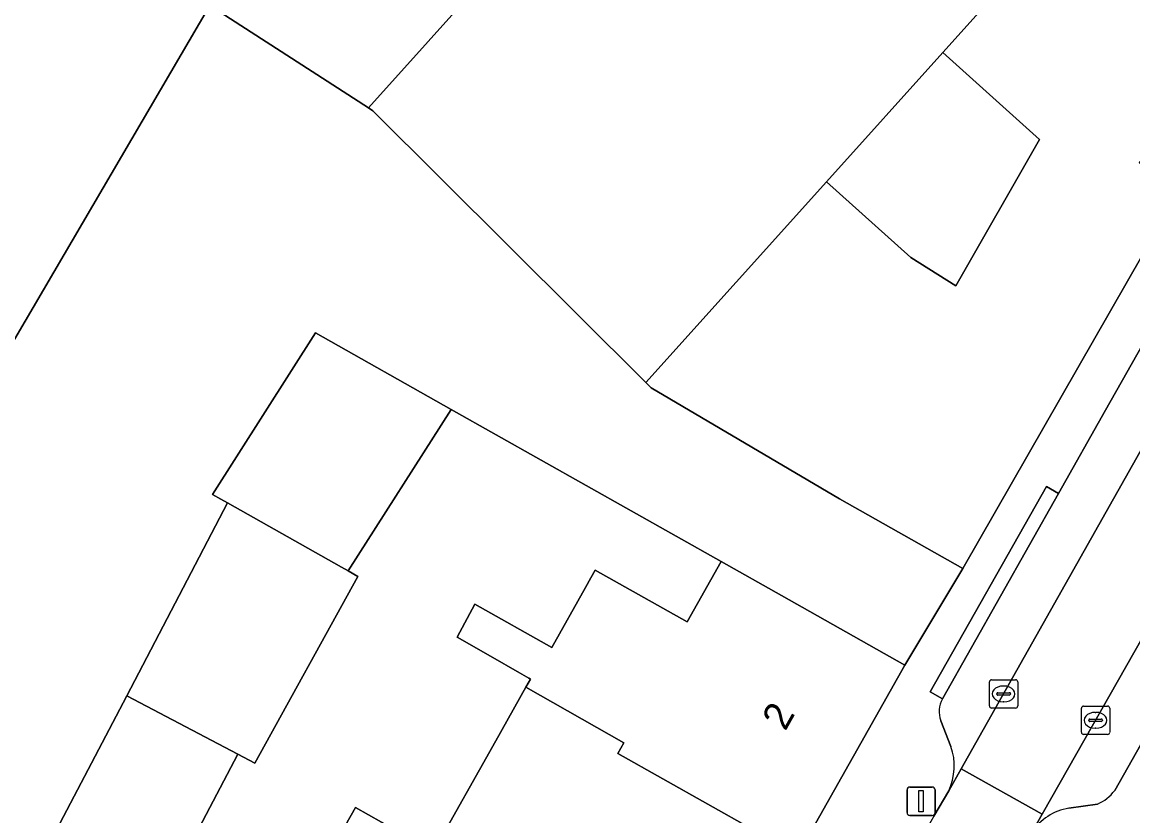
# Model space of a CAD drawing. Extents: x 161798 to 162385, y 382315 to 382833.
# Drawn here: x 161998.86 to 162038.1, y 382696.04 to 382724.06 of the extents above; entities that cross this region are included whole.
import ezdxf

# ---------------------------------------------------------------- set-up
doc = ezdxf.new("R2010")
doc.units = 0
for name, color, linetype in [('IMGEO_Erf', 7, 'Continuous'), ('IMGEO_Kolk', 7, 'Continuous'), ('IMGEO_Lichtmast', 7, 'Continuous'), ('IMGEO_Pand', 7, 'Continuous'), ('IMGEO_Pand_nummerreeks', 7, 'Continuous'), ('IMGEO_Parkeervlak_open', 7, 'Continuous'), ('IMGEO_Rijbaan_lokaal_open', 7, 'Continuous'), ('IMGEO_Voetpad_open', 7, 'Continuous')]:
    doc.layers.add(name, color=color, linetype=linetype)

msp = doc.modelspace()

# ---------------------------------------------------------------- linework, layer by layer
at = {"layer": 'IMGEO_Erf'}
for points in [[(161996.854, 382709.902), (162005.49, 382724.651), (162000, 382728.195), (161996.847, 382730.23), (162000, 382733.772), (162004.032, 382738.302), (161999.682, 382742.186), (161998.309, 382743.412), (162000, 382745.307), (162001.581, 382747.078), (162000, 382748.49), (161998.309, 382750)], [(162009.735, 382694.733), (162010.637, 382696.335), (162013.398, 382694.78), (162015.595, 382698.684), (162016.663, 382700.581), (162016.823, 382700.865), (162016.766, 382700.898), (162016.434, 382701.087), (162015.405, 382701.673), (162014.233, 382702.34), (162014.854, 382703.511), (162017.571, 382701.981), (162018.762, 382704.095), (162018.959, 382704.445), (162019.109, 382704.711), (162022.353, 382702.884), (162023.554, 382705.016), (162014.021, 382710.386), (162010.382, 382704.681), (162010.717, 382704.492), (162007.082, 382697.894), (162006.484, 382698.209), (162003.37, 382692.292)]]:
    msp.add_lwpolyline(points, dxfattribs=at)
msp.add_lwpolyline([(162031.391, 382722.985), (162027.277, 382718.416), (162030.255, 382715.747), (162031.855, 382714.755), (162034.809, 382719.922)], close=True, dxfattribs=at)
at = {"layer": 'IMGEO_Kolk'}
for p, q in [((162033.037, 382699.914), (162033.037, 382700.766)), ((162033.112, 382700.84), (162033.964, 382700.84)), ((162033.525, 382700.62), (162033.55, 382700.62)), ((162034.038, 382700.766), (162034.038, 382699.914)), ((162033.296, 382700.334), (162033.296, 382700.346)), ((162033.734, 382700.297), (162033.336, 382700.297)), ((162033.339, 382700.383), (162033.737, 382700.383)), ((162033.78, 382700.346), (162033.78, 382700.334)), ((162033.964, 382699.84), (162033.112, 382699.84)), ((162033.548, 382700.06), (162033.523, 382700.06)), ((162036.286, 382698.984), (162036.286, 382699.836)), ((162036.361, 382699.91), (162037.213, 382699.91)), ((162037.287, 382699.836), (162037.287, 382698.984)), ((162036.588, 382699.453), (162036.986, 382699.453)), ((162036.774, 382699.69), (162036.799, 382699.69)), ((162036.545, 382699.404), (162036.545, 382699.416)), ((162036.983, 382699.367), (162036.585, 382699.367)), ((162036.797, 382699.13), (162036.772, 382699.13)), ((162037.029, 382699.416), (162037.029, 382699.404)), ((162037.213, 382698.91), (162036.361, 382698.91))]:
    msp.add_line(p, q, dxfattribs=at)
for points in [[(162033.037, 382699.914), (162033.037, 382700.766)], [(162033.112, 382700.84), (162033.964, 382700.84)], [(162034.038, 382700.766), (162034.038, 382699.914)], [(162033.964, 382699.84), (162033.112, 382699.84)], [(162036.286, 382698.984), (162036.286, 382699.836)], [(162036.361, 382699.91), (162037.213, 382699.91)], [(162037.287, 382699.836), (162037.287, 382698.984)], [(162037.213, 382698.91), (162036.361, 382698.91)]]:
    msp.add_lwpolyline(points, dxfattribs=at)
for centre, radius, start, end in [((162033.114, 382700.764), 0.0765, 91.552, 178.448), ((162033.114, 382700.764), 0.0765, 91.552, 178.448), ((162033.962, 382700.764), 0.0765, 1.552, 88.448), ((162033.962, 382700.764), 0.0765, 1.552, 88.448), ((162033.336, 382700.343), 0.0403, 85.8775, 175.7526), ((162033.333, 382700.333), 0.0366, 178.938, 274.7102), ((162033.737, 382700.34), 0.043, 264.8664, 352.4533), ((162033.741, 382700.345), 0.0386, 1.7309, 96.639), ((162033.114, 382699.916), 0.0765, 181.552, 268.448), ((162033.114, 382699.916), 0.0765, 181.552, 268.448), ((162033.962, 382699.916), 0.0765, 271.552, 358.448), ((162033.962, 382699.916), 0.0765, 271.552, 358.448), ((162036.363, 382699.834), 0.0765, 91.552, 178.448), ((162036.363, 382699.834), 0.0765, 91.552, 178.448), ((162037.211, 382699.834), 0.0765, 1.552, 88.448), ((162037.211, 382699.834), 0.0765, 1.552, 88.448), ((162036.585, 382699.413), 0.0403, 85.8775, 175.7526), ((162036.99, 382699.415), 0.0386, 1.7309, 96.639), ((162036.582, 382699.403), 0.0366, 178.938, 274.7102), ((162036.986, 382699.41), 0.043, 264.8664, 352.4533), ((162036.363, 382698.986), 0.0765, 181.552, 268.448), ((162036.363, 382698.986), 0.0765, 181.552, 268.448), ((162037.211, 382698.986), 0.0765, 271.552, 358.448), ((162037.211, 382698.986), 0.0765, 271.552, 358.448)]:
    msp.add_arc(centre, radius, start, end, dxfattribs=at)
for centre, major_axis, ratio, start_param, end_param in [((162033.524, 382700.34), (-0.387, 0.002), 0.722429, 4.712389, 7.853982), ((162033.549, 382700.34), (-0.39, 0.002), 0.717154, 1.570796, 4.712389), ((162036.773, 382699.41), (-0.387, 0.002), 0.722429, 4.712389, 7.853982), ((162036.798, 382699.41), (-0.39, 0.002), 0.717154, 1.570796, 4.712389)]:
    msp.add_ellipse(centre, major_axis=major_axis, ratio=ratio, start_param=start_param, end_param=end_param, dxfattribs=at)
at = {"layer": 'IMGEO_Lichtmast'}
for p, q in [((162030.127, 382696.15), (162030.127, 382696.95)), ((162030.127, 382696.95), (162030.127, 382696.15)), ((162030.227, 382697.05), (162031.017, 382697.05)), ((162031.017, 382697.05), (162030.227, 382697.05)), ((162031.117, 382696.95), (162031.117, 382696.15)), ((162031.117, 382696.15), (162031.117, 382696.95)), ((162031.017, 382696.05), (162030.227, 382696.05)), ((162030.227, 382696.05), (162031.017, 382696.05))]:
    msp.add_line(p, q, dxfattribs=at)
msp.add_lwpolyline([(162030.547, 382696.925), (162030.697, 382696.925), (162030.697, 382696.175), (162030.547, 382696.175), (162030.547, 382696.925)], dxfattribs=at)
for centre, start, end in [((162030.227, 382696.95), 90, 180), ((162030.227, 382696.95), 90, 180), ((162031.017, 382696.95), 0, 90), ((162031.017, 382696.95), 360, 90), ((162030.227, 382696.15), 180, 270), ((162030.227, 382696.15), 180, 270), ((162031.017, 382696.15), 270, 0), ((162031.017, 382696.15), 270, 0)]:
    msp.add_arc(centre, 0.1, start, end, dxfattribs=at)
at = {"layer": 'IMGEO_Pand'}
for points in [[(162027.754, 382739.543), (162022.858, 382743.945), (162005.49, 382724.651), (162011.093, 382721.034)], [(162038.012, 382730.344), (162027.754, 382739.543), (162011.093, 382721.034), (162011.249, 382720.933), (162020.899, 382711.331), (162027.277, 382718.416), (162031.391, 382722.985)], [(162043.809, 382725.145), (162038.012, 382730.344), (162031.391, 382722.985), (162034.809, 382719.922), (162031.855, 382714.755), (162030.255, 382715.747), (162027.277, 382718.416), (162020.899, 382711.331), (162021.086, 382711.145), (162027.742, 382707.225), (162032.096, 382704.768), (162039.623, 382717.887), (162038.323, 382719.109)], [(162014.021, 382710.386), (162009.229, 382713.086), (162005.59, 382707.381), (162005.878, 382707.219), (162006.112, 382707.087), (162010.142, 382704.816), (162010.382, 382704.681)], [(162010.382, 382704.681), (162010.142, 382704.816), (162006.112, 382707.087), (162002.565, 382700.272), (162006.484, 382698.209), (162007.082, 382697.894), (162010.717, 382704.492)], [(162030.046, 382701.359), (162025.696, 382703.81), (162023.554, 382705.016), (162022.353, 382702.884), (162019.109, 382704.711), (162018.959, 382704.445), (162018.762, 382704.095), (162017.571, 382701.981), (162014.854, 382703.511), (162014.233, 382702.34), (162015.405, 382701.673), (162016.434, 382701.087), (162016.766, 382700.898), (162016.823, 382700.865), (162016.663, 382700.581), (162020.124, 382698.61), (162019.913, 382698.235), (162026.271, 382694.655)], [(161999.451, 382694.354), (162003.37, 382692.292), (162006.484, 382698.209), (162002.565, 382700.272)], [(162019.913, 382698.235), (162020.124, 382698.61), (162016.663, 382700.581), (162015.595, 382698.684), (162013.398, 382694.78), (162016.519, 382693.02), (162016.864, 382692.826), (162017.314, 382693.625), (162020.278, 382691.955), (162019.089, 382689.844), (162022.485, 382687.932), (162026.271, 382694.655)], [(162017.314, 382693.625), (162016.864, 382692.826), (162016.519, 382693.02), (162013.398, 382694.78), (162010.637, 382696.335), (162009.735, 382694.733), (162012.033, 382693.437), (162012.402, 382693.23), (162012.495, 382693.177), (162009.858, 382688.493), (162010.234, 382688.281), (162013.156, 382686.635), (162019.684, 382682.959), (162022.485, 382687.932), (162019.089, 382689.844), (162020.278, 382691.955)]]:
    msp.add_lwpolyline(points, close=True, dxfattribs=at)
at = {"layer": 'IMGEO_Parkeervlak_open'}
for points in [[(162031.601, 382696.918), (162032.04, 382697.695), (162045.858, 382722.165)], [(162043.019, 382720.833), (162041.66, 382718.336), (162037.138, 382710.354), (162035.478, 382707.418), (162031.379, 382700.168)], [(162046.73, 382716.896), (162034.906, 382696.099), (162034.536, 382695.447)], [(162037.462, 382696.935), (162042.426, 382705.699), (162046.814, 382713.629)], [(162031.317, 382699.395), (162031.677, 382698.482)], [(162035.844, 382696.305), (162036.853, 382696.447)]]:
    msp.add_lwpolyline(points, dxfattribs=at)
for centre, radius, start, end in [((162032.184, 382699.714), 0.924, 150.6151, 200.2135), ((162029.717, 382697.793), 2.078, 335.0806, 19.3554), ((162036.288, 382697.776), 1.444, 293.027, 324.3843), ((162036.132, 382694.44), 1.887, 98.7742, 147.7526)]:
    msp.add_arc(centre, radius, start, end, dxfattribs=at)
at = {"layer": 'IMGEO_Rijbaan_lokaal_open'}
msp.add_lwpolyline([(161992.884, 382681.874), (161999.451, 382694.354), (162002.565, 382700.272), (162006.112, 382707.087), (162005.878, 382707.219), (162005.59, 382707.381), (162009.229, 382713.086), (162014.021, 382710.386), (162023.554, 382705.016), (162025.696, 382703.81), (162030.046, 382701.359), (162032.096, 382704.768), (162027.742, 382707.225), (162021.086, 382711.145), (162020.899, 382711.331), (162011.249, 382720.933), (162011.093, 382721.034), (162005.49, 382724.651), (161996.854, 382709.902)], dxfattribs=at)
for points in [[(162046.73, 382716.896), (162048.367, 382719.786), (162048.416, 382719.879), (162045.858, 382722.165), (162032.04, 382697.695), (162034.906, 382696.099)], [(162034.906, 382696.099), (162032.04, 382697.695), (162031.601, 382696.918), (162031.076, 382696.025), (162030.647, 382695.267), (162033.513, 382693.664), (162034.536, 382695.447)]]:
    msp.add_lwpolyline(points, close=True, dxfattribs=at)
at = {"layer": 'IMGEO_Voetpad_open'}
for points in [[(162045.819, 382722.219), (162043.809, 382725.145), (162038.323, 382719.109), (162039.623, 382717.887), (162032.096, 382704.768), (162030.046, 382701.359), (162026.271, 382694.655), (162022.485, 382687.932), (162019.684, 382682.959), (162015.615, 382675.734), (162015.046, 382674.723), (162012.489, 382670.184), (162009.351, 382664.611), (162005.425, 382657.64), (162002.666, 382652.742), (162000, 382648.009), (161998.381, 382645.135), (161995.375, 382646.828), (161994.867, 382646.022), (161990.55, 382641.902), (161994.605, 382633.896), (161994.989, 382632.3)], [(162031.379, 382700.168), (162030.945, 382700.414), (162035.052, 382707.66), (162035.478, 382707.418), (162037.138, 382710.354), (162041.66, 382718.336), (162043.019, 382720.833)], [(162046.814, 382713.629), (162042.426, 382705.699), (162037.462, 382696.935)], [(162031.677, 382698.482), (162031.317, 382699.395)], [(162031.076, 382696.025), (162031.601, 382696.918)], [(162036.853, 382696.447), (162035.844, 382696.305)]]:
    msp.add_lwpolyline(points, dxfattribs=at)
msp.add_lwpolyline([(162035.478, 382707.418), (162035.052, 382707.66), (162030.945, 382700.414), (162031.379, 382700.168)], close=True, dxfattribs=at)
for centre, radius, start, end in [((162032.184, 382699.714), 0.924, 150.6151, 200.2135), ((162029.717, 382697.793), 2.078, 335.0806, 19.3554), ((162036.288, 382697.776), 1.444, 293.027, 324.3843), ((162036.132, 382694.44), 1.887, 98.7742, 147.7526)]:
    msp.add_arc(centre, radius, start, end, dxfattribs=at)

# ---------------------------------------------------------------- texts
at = {"layer": 'IMGEO_Pand_nummerreeks'}
msp.add_text('2', height=1, rotation=60.6132, dxfattribs=at).set_placement((162025.825, 382699.002))

doc.saveas('drawing.dxf')
